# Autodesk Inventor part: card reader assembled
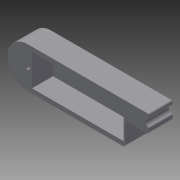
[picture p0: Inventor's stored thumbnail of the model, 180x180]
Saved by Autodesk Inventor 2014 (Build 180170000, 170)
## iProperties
Created: 2015-01
Part Number: card reader assembled
Material: Generic
Document SubType Name: Modeling
Designer: Drano
Density: 1 g/cm^3
Appearance: Default
Author: Drano
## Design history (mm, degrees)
derived "card reader.iam"
body "Solid1"
node "backplate.ipt:1" dims "d0" = 10
node "card reader.ipt:1" dims "d0" = 10
node "card reader.iam_Bodies" dims "d0" = 10
